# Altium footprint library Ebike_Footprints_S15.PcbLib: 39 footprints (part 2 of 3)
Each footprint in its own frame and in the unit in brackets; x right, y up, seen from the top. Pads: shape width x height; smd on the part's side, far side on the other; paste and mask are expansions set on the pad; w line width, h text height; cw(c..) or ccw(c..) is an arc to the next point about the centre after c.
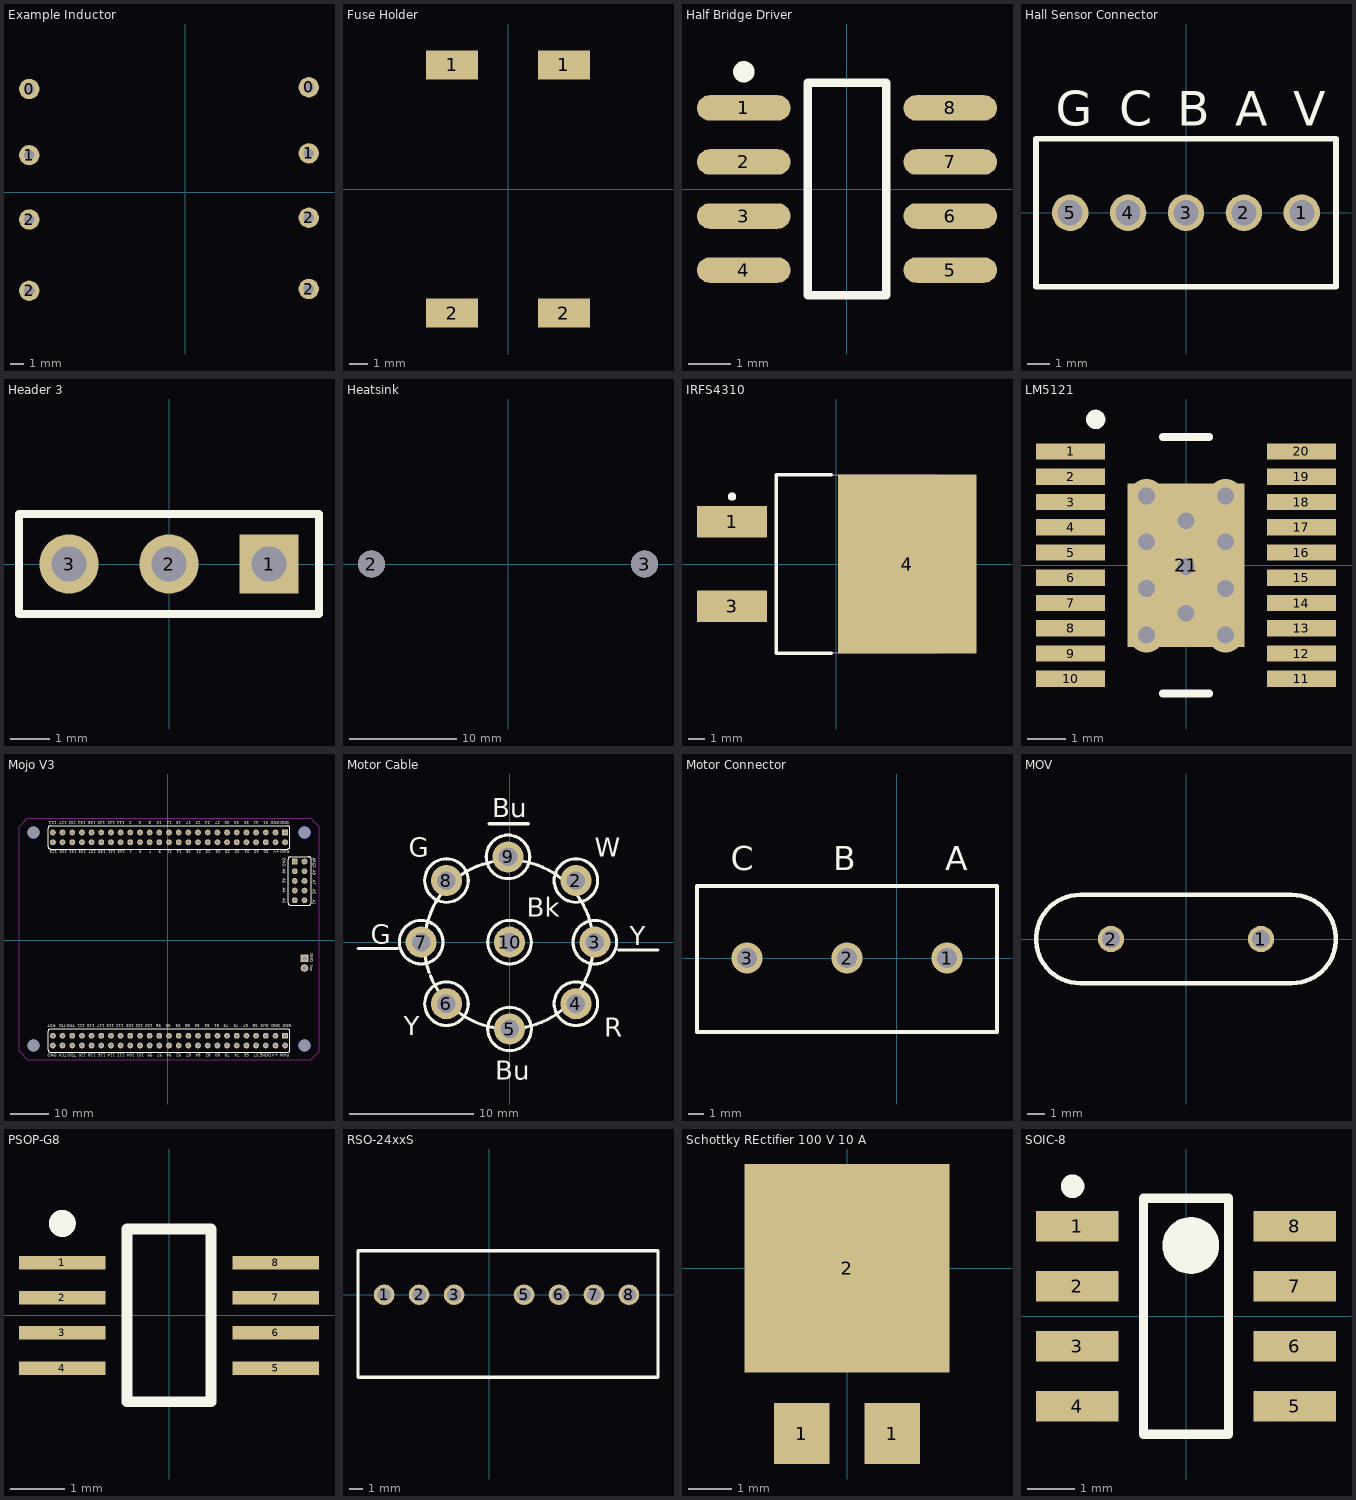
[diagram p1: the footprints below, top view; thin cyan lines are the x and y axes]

## Example Inductor [mil] "Coilcraft-FA2890-AL"
pads (8):
  round 60 hole 30: 0(-460,305) 0(365,310) 1(-460,110) 1(365,115) 2(-460,-290) 2(-460,-80) 2(365,-285) 2(365,-75)
3D body: height 830.71, standoff -127.36, extent -612.05,-497.6 510,527.6

## Fuse Holder [mm] "ATO/ATC 0.752\" Fuse"
pads (4):
  rect 2.82x1.57 smd: 1(-3.03,6.73) 1(3.03,6.73) 2(-3.03,-6.73) 2(3.03,-6.73)
3D body: height 11.1, standoff 0.5, extent -4.064,-8.763 4.318,9.017

## Half Bridge Driver [mm] "LM5104, 8-SOIC"
height 1.75
pads (8):
  oval 2.2x0.6 smd: 1(-2.425,1.905) 2(-2.425,0.635) 3(-2.425,-0.635) 4(-2.425,-1.905) 5(2.425,-1.905) 6(2.425,-0.635) 7(2.425,0.635) 8(2.425,1.905)
Top Overlay:
  circle w0.25: c-2.425,2.755 r0.125
  lines w0.2: -0.925,-2.5 -0.925,2.5 0.925,2.5 0.925,-2.5 -0.925,-2.5
3D body: height 1.75, standoff 0.1, extent -2,-2.5 2,2.5

## Hall Sensor Connector [mm] "Phoenix 5-terminal Block Screw connector"
pads (5):
  round 1.6 hole 1.1: 1(5.08,0) 2(2.54,0) 3(0,0) 4(-2.54,0) 5(-5.08,0)
Top Overlay:
  lines w0.254: -6.58,-3.25 6.58,-3.25 6.58,3.25 -6.58,3.25 -6.58,-3.25
  text "G" at -5.715,3.81 h1.52
  text "A" at 2.159,3.81 h1.52
  text "V" at 4.699,3.81 h1.52
  text "B" at -0.381,3.81 h1.52
  text "C" at -2.921,3.81 h1.52
3D body: height 3.5, standoff -8.5, extent -6.731,-3.175 6.429,3.025

## Header 3 [mm]
pads (3):
  rect 1.5x1.5 hole 0.9: 1(2.54,0)
  round 1.5 hole 0.9: 2(0,0) 3(-2.54,0)
Top Overlay:
  lines w0.2: -3.81,-1.27 3.81,-1.27 3.81,1.27 -3.81,1.27 -3.81,-1.27
3D body: height 5.5, standoff -6.04, extent -1.143,-1.27 3.937,1.27
3D body: height 5.5, standoff -6.04, extent -3.937,-1.27 1.143,1.27

## Heatsink [mm] "Aavid 530002B02500G"
pads (2):
  round 2.5 hole 2.5: 2(-12.7,0) 3(12.7,0)
3D body: height 63.5, standoff -3.8, extent -21.153,-13.074 20.447,12.058

## IRFS4310 [mm] "D2-PAK, 3-Pads, Body 9.6x10.7mm (max), IPC Medium Density"
height 4.83
pads (3):
  rect 4.2x1.9 smd: 1(-6.25,2.54) 3(-6.25,-2.54)
  rect 8.3x10.75 smd: 4(4.25,0)
Top Overlay:
  circle w0.25: c-6.25,4.04 r0.125
  lines w0.2: -0.3,-5.35 -3.6,-5.35 -3.6,5.35 -0.3,5.35
Mechanical 13:
  lines w0.1: -3.6,-5.325 6.05,-5.325 6.05,5.325 -3.6,5.325 -3.6,-5.325
3D body: height -0.37, standoff -5.38, extent -7.771,-4.953 7.493,5.207

## LM5121 [mm] "PWP0020A, 20 pin HTSSOP with thermal pad"
height 1.1
pads (21):
  rect 1.78x0.42 smd: 1(-2.97,2.925) 2(-2.97,2.275) 3(-2.97,1.625) 4(-2.97,0.975) 5(-2.97,0.325) 6(-2.97,-0.325) 7(-2.97,-0.975) 8(-2.97,-1.625) 9(-2.97,-2.275) 10(-2.97,-2.925) 11(2.97,-2.925) 12(2.97,-2.275) 13(2.97,-1.625) 14(2.97,-0.975) 15(2.97,-0.325) 16(2.97,0.325) 17(2.97,0.975) 18(2.97,1.625) 19(2.97,2.275) 20(2.97,2.925)
  rect 3x4.2 smd: 21(0,0)
via 1.016,0.6 diameter 0.889 hole 0.432
via 1.016,-0.6 diameter 0.889 hole 0.432
via 1.016,-1.8 diameter 0.889 hole 0.432
via 1.016,1.778 diameter 0.889 hole 0.432
via 0,-0.035 diameter 0.889 hole 0.432
via 0,-1.235 diameter 0.889 hole 0.432
via 0,1.143 diameter 0.889 hole 0.432
via -1.016,0.6 diameter 0.889 hole 0.432
via -1.016,-0.6 diameter 0.889 hole 0.432
via -1.016,-1.8 diameter 0.889 hole 0.432
via -1.016,1.778 diameter 0.889 hole 0.432
Top Overlay:
  circle w0.25: c-2.325,3.75 r0.125
  lines w0.2: -0.6,-3.3 0.6,-3.3 ; -0.6,3.3 0.6,3.3
3D body: height 1.1, standoff 0.1, extent -2.25,-3.3 2.25,3.3

## Mojo V3 [mil]
pads (116):
  rect 60x60 hole 36: 1(1211.26,1115) 51(1211.26,-985) 101(1311.26,815)
  round 60 hole 36: 2(1211.26,1015) 3(1111.26,1115) 4(1111.26,1015) 5(1011.26,1115) 6(1011.26,1015) 7(911.26,1115) 8(911.26,1015) 9(811.26,1115) 10(811.26,1015) 11(711.26,1115) 12(711.26,1015) 13(611.26,1115) 14(611.26,1015) 15(511.26,1115) 16(511.26,1015) 17(411.26,1115) 18(411.26,1015) 19(311.26,1115) 20(311.26,1015) 21(211.26,1115) 22(211.26,1015) 23(111.26,1115) 24(111.26,1015) 25(11.26,1115) 26(11.26,1015) 27(-88.74,1115) 28(-88.74,1015) 29(-188.74,1115) 30(-188.74,1015) 31(-288.74,1115) 32(-288.74,1015) 33(-388.74,1115) 34(-388.74,1015) 35(-488.74,1115) 36(-488.74,1015) 37(-588.74,1115) 38(-588.74,1015) 39(-688.74,1115) 40(-688.74,1015) 41(-788.74,1115) 42(-788.74,1015) 43(-888.74,1115) 44(-888.74,1015) 45(-988.74,1115) 46(-988.74,1015) 47(-1088.74,1115) 48(-1088.74,1015) 49(-1188.74,1115) 50(-1188.74,1015) 52(1211.26,-1085) 53(1111.26,-985) 54(1111.26,-1085) 55(1011.26,-985) 56(1011.26,-1085) 57(911.26,-985) 58(911.26,-1085) 59(811.26,-985) 60(811.26,-1085) 61(711.26,-985) 62(711.26,-1085) 63(611.26,-985) 64(611.26,-1085) 65(511.26,-985) 66(511.26,-1085) 67(411.26,-985) 68(411.26,-1085) 69(311.26,-985) 70(311.26,-1085) 71(211.26,-985) 72(211.26,-1085) 73(111.26,-985) 74(111.26,-1085) 75(11.26,-985) 76(11.26,-1085) 77(-88.74,-985) 78(-88.74,-1085) 79(-188.74,-985) 80(-188.74,-1085) 81(-288.74,-985) 82(-288.74,-1085) 83(-388.74,-985) 84(-388.74,-1085) 85(-488.74,-985) 86(-488.74,-1085) 87(-588.74,-985) 88(-588.74,-1085) 89(-688.74,-985) 90(-688.74,-1085) 91(-788.74,-985) 92(-788.74,-1085) 93(-888.74,-985) 94(-888.74,-1085) 95(-988.74,-985) 96(-988.74,-1085) 97(-1088.74,-985) 98(-1088.74,-1085) 99(-1188.74,-985) 100(-1188.74,-1085) 102(1411.26,815) 103(1311.26,715) 104(1411.26,715) 105(1311.26,615) 106(1411.26,615) 107(1311.26,515) 108(1411.26,515) 109(1311.26,415) 110(1411.26,415)
  rect 78.74x78.74 hole 50: 120(1411.26,-185.04)
  round 78.74 hole 50: 121(1411.26,-285.04)
  round 125.98 smd far side: ""(-1388.74,-1085) ""(-1388.74,1115) ""(1411.26,-1085) ""(1411.26,1115)
Top Overlay:
  lines w6: -1238.74,-1130 ccw(c-1213.74,-1130) -1213.74,-1155 1236.26,-1155 ccw(c1236.26,-1130) 1261.26,-1130 1261.26,-940 ccw(c1236.26,-940) 1236.26,-915 -1213.74,-915 ccw(c-1213.74,-940) -1238.74,-940 -1238.74,-1130 ; -1238.74,970 ccw(c-1213.74,970) -1213.74,945 1236.26,945 ccw(c1236.26,970) 1261.26,970 1261.26,1160 ccw(c1236.26,1160) 1236.26,1185 -1213.74,1185 ccw(c-1213.74,1160) -1238.74,1160 -1238.74,970 ; 1241.26,390 ccw(c1266.26,390) 1266.26,365 1456.26,365 ccw(c1456.26,390) 1481.26,390 1481.26,840 ccw(c1456.26,840) 1456.26,865 1266.26,865 ccw(c1266.26,840) 1241.26,840 1241.26,390
  text "DONE" at 1068.27,-1170 h32
  text "SUS" at 1043.5,-867.42 h32
  text "TCK" at -1047.38,-1170 h32
  text "TDI" at -1057.38,-867.42 h32
  text "GND" at -1147.38,-1170 h32
  text "RST" at -1157.38,-867.42 h32
  text "TDO" at -947.38,-1170 h32
  text "TMS" at -957.38,-867.42 h32
  text "RAW" at 1253.9,-1170 h32
  text "118" at -744.72,-1170 h32
  text "119" at -754.72,-867.42 h32
  text "120" at -844.72,-1170 h32
  text "121" at -854.72,-867.42 h32
  text "116" at -644.72,-1170 h32
  text "117" at -654.72,-867.42 h32
  text "114" at -544.72,-1170 h32
  text "115" at -554.72,-867.42 h32
  text "111" at -444.72,-1170 h32
  text "112" at -454.72,-867.42 h32
  text "104" at -344.72,-1170 h32
  text "105" at -354.72,-867.42 h32
  text "101" at -244.72,-1170 h32
  text "102" at -254.72,-867.42 h32
  text "99" at -157.22,-1170 h32
  text "100" at -154.72,-867.42 h32
  text "97" at -59.69,-1170 h32
  text "98" at -69.69,-867.42 h32
  text "94" at 40.31,-1170 h32
  text "95" at 30.31,-867.42 h32
  text "92" at 140.31,-1170 h32
  text "93" at 130.31,-867.42 h32
  text "87" at 240.31,-1170 h32
  text "88" at 230.31,-867.42 h32
  text "84" at 340.31,-1170 h32
  text "85" at 330.31,-867.42 h32
  text "82" at 440.31,-1170 h32
  text "83" at 430.31,-867.42 h32
  text "80" at 540.31,-1170 h32
  text "81" at 530.31,-867.42 h32
  text "78" at 640.32,-1170 h32
  text "79" at 630.32,-867.42 h32
  text "74" at 740.32,-1170 h32
  text "75" at 730.32,-867.42 h32
  text "66" at 840.32,-1170 h32
  text "67" at 830.32,-867.42 h32
  text "57" at 940.32,-1170 h32
  text "58" at 930.32,-867.42 h32
  text "GND" at 1278.74,-867.42 h32
  text "+V" at 1141.4,-1170 h32
  text "51" at 1038.74,1232.58 h32
  text "9" at -68.76,930 h32
  text "7" at -168.76,930 h32
  text "8" at -173.76,1232.58 h32
  text "40" at 943.74,930 h32
  text "50" at 1043.74,930 h32
  text "+V" at 1156.24,930 h32
  text "41" at 938.74,1232.58 h32
  text "GND" at 1153.9,1232.58 h32
  text "29" at 643.74,930 h32
  text "32" at 743.74,930 h32
  text "34" at 843.74,930 h32
  text "30" at 638.74,1232.58 h32
  text "33" at 738.74,1232.58 h32
  text "35" at 838.74,1232.58 h32
  text "21" at 343.74,930 h32
  text "23" at 443.74,930 h32
  text "22" at 338.74,1232.58 h32
  text "24" at 438.74,1232.58 h32
  text "11" at 43.74,930 h32
  text "14" at 143.74,930 h32
  text "12" at 38.74,1232.58 h32
  text "15" at 138.74,1232.58 h32
  text "1" at -368.76,930 h32
  text "5" at -268.76,930 h32
  text "2" at -373.76,1232.58 h32
  text "6" at -273.76,1232.58 h32
  text "141" at -541.3,930 h32
  text "143" at -441.3,930 h32
  text "142" at -546.3,1232.58 h32
  text "144" at -446.3,1232.58 h32
  text "131" at -942.38,930 h32
  text "133" at -842.38,930 h32
  text "137" at -741.3,930 h32
  text "132" at -947.38,1232.58 h32
  text "134" at -847.38,1232.58 h32
  text "138" at -746.3,1232.58 h32
  text "123" at -1142.38,930 h32
  text "124" at -1147.38,1232.58 h32
  text "GND" at 1254.78,1232.58 h32
  text "16" at 243.74,930 h32
  text "26" at 543.74,930 h32
  text "10" at -61.26,1232.58 h32
  text "17" at 238.74,1232.58 h32
  text "27" at 538.74,1232.58 h32
  text "126" at -1042.38,930 h32
  text "139" at -641.3,930 h32
  text "127" at -1047.38,1232.58 h32
  text "140" at -646.3,1232.58 h32
  text "RAW" at 1259.78,930.79 h32
  text "GND" at 1158.74,-867.42 h32
  text "AREF" at 1498.6,854.92 h32
  text "GND" at 1187.72,855.16 h32
  text "A8" at 1187.72,738.43 h32
  text "A7" at 1498.6,626.57 h32
  text "A6" at 1187.72,641.57 h32
  text "A5" at 1498.6,529.72 h32
  text "A4" at 1187.72,544.72 h32
  text "A1" at 1498.6,423.03 h32
  text "A9" at 1498.6,723.43 h32
  text "A0" at 1187.72,438.03 h32
  text "Vcc" at 1470,-250 h32
  text "GND" at 1470,-130 h32
Drill Guide:
  drawing of 220 lines, arcs and shapes, not listed
Keep-Out Layer:
  lines w0.31: -1538.74,-1147.5 -1451.24,-1235 1473.76,-1235 1561.26,-1147.5 1561.26,1177.5 1473.76,1265 -1451.24,1265 -1538.74,1177.5 -1538.74,-1147.5
Mechanical 1:
  text "Component Side" at 407.52,-20 h60

## Motor Cable [mm]
height 5.6
pads (9):
  round 2.5 hole 1.5: 2(5.334,4.953) 3(6.858,0) 4(5.334,-4.953) 5(0,-6.985) 6(-5.08,-4.953) 7(-7.112,0) 8(-5.08,4.953) 9(-0.127,6.858) 10(0,0)
Top Overlay:
  circle w0.254: c5.334,4.953 r1.75
  circle w0.254: c-5.08,-4.953 r1.75
  circle w0.254: c0,-6.985 r1.75
  circle w0.254: c-5.08,4.953 r1.75
  circle w0.254: c0,0 r1.75
  circle w0.254: c5.334,-4.953 r1.75
  circle w0.254: c-7.112,0 r1.75
  circle w0.254: c6.858,0 r1.75
  circle w0.254: c-0.127,6.858 r1.75
  lines w0.254: -12.192,-0.508 -9.017,-0.508 ; -6.465,-2.446 cw(c-0.063,-0.19) -6.372,-2.696 ; -1.651,9.525 1.524,9.525 ; 8.763,-0.635 11.938,-0.635
  text "W" at 6.858,6.858 h1.52
  text "Bu" at -1.143,-11.049 h1.52
  text "Bu" at -1.397,10.033 h1.52
  text "Bk" at 1.397,2.032 h1.52
  text "R" at 7.62,-7.62 h1.52
  text "Y" at -8.509,-7.493 h1.52
  text "G" at -8.128,6.858 h1.52
  text "Y" at 9.652,-0.254 h1.52
  text "G" at -11.176,-0.127 h1.52

## Motor Connector [mm] "Phoenix 3-terminal Block Screw connector"
pads (3):
  round 2 hole 1.3: 1(3.175,0) 2(-3.175,0) 3(-9.525,0)
Top Overlay:
  lines w0.254: -12.7,-4.699 6.35,-4.699 6.35,4.572 -12.7,4.572 -12.7,-4.699
  text "A" at 3.048,5.588 h1.52
  text "B" at -4.064,5.588 h1.52
  text "C" at -10.541,5.588 h1.52
3D body: height 15.2, standoff -3.5, extent -10.548,-4.555 4.452,4.445

## MOV [mm] "ZA Series MOXV"
pads (2):
  round 1.5 hole 1: 1(4.25,0) 2(-4.25,0)
Top Overlay:
  lines w0.254: -6,-2.5 cw(c-6,0) -6,2.5 6,2.5 cw(c6,0) 6,-2.5 -6,-2.5

## PSOP-G8 [mm] "SOP127P600-8N"
height 1.3
pads (8):
  rect 1.6x0.25 smd: 1(-1.975,0.975) 2(-1.975,0.325) 3(-1.975,-0.325) 4(-1.975,-0.975) 5(1.975,-0.975) 6(1.975,-0.325) 7(1.975,0.325) 8(1.975,0.975)
Top Overlay:
  circle w0.25: c-1.975,1.7 r0.125
  lines w0.2: -0.775,-1.6 0.775,-1.6 0.775,1.6 -0.775,1.6 -0.775,-1.6
3D body: height 1.3, standoff 0, extent -1.45,-1.575 1.45,1.575

## RSO-24xxS [mm] "Isolated 18-36Vin, 2W, xxVout"
pads (7):
  round 1.5 hole 1: 1(-7.62,0) 2(-5.08,0) 3(-2.54,0) 5(2.54,0) 6(5.08,0) 7(7.62,0) 8(10.16,0)
Top Overlay:
  lines w0.254: -9.525,-6 12.275,-6 12.275,3.2 -9.525,3.2 -9.525,-6
3D body: height 11.1, standoff 0.5, extent -9.525,-5.969 12.319,3.175

## Schottky REctifier 100 V 10 A [mm] "V10P10"
pads (3):
  rect 1.27x1.4 smd: 1(-1.04,-3.805) 1(1.04,-3.805)
  rect 4.72x4.8 smd: 2(0,0)
3D body: height 3, standoff 0.38, extent -2.413,-3.302 2.413,2.159

## SOIC-8 [mm] "ACS714 Hall Sensor"
height 1.75
pads (8):
  rect 1.75x0.65 smd: 1(-2.3,1.905) 2(-2.3,0.635) 3(-2.3,-0.635) 4(-2.3,-1.905) 5(2.3,-1.905) 6(2.3,-0.635) 7(2.3,0.635) 8(2.3,1.905)
Top Overlay:
  circle w0.25: c-2.4,2.755 r0.125
  circle w0.6: c0.1,1.5 r0.3
  lines w0.2: -0.9,-2.5 -0.9,2.5 0.9,2.5 0.9,-2.5 -0.9,-2.5
3D body: height 1.75, standoff 0.1, extent -2,-2.5 2,2.5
